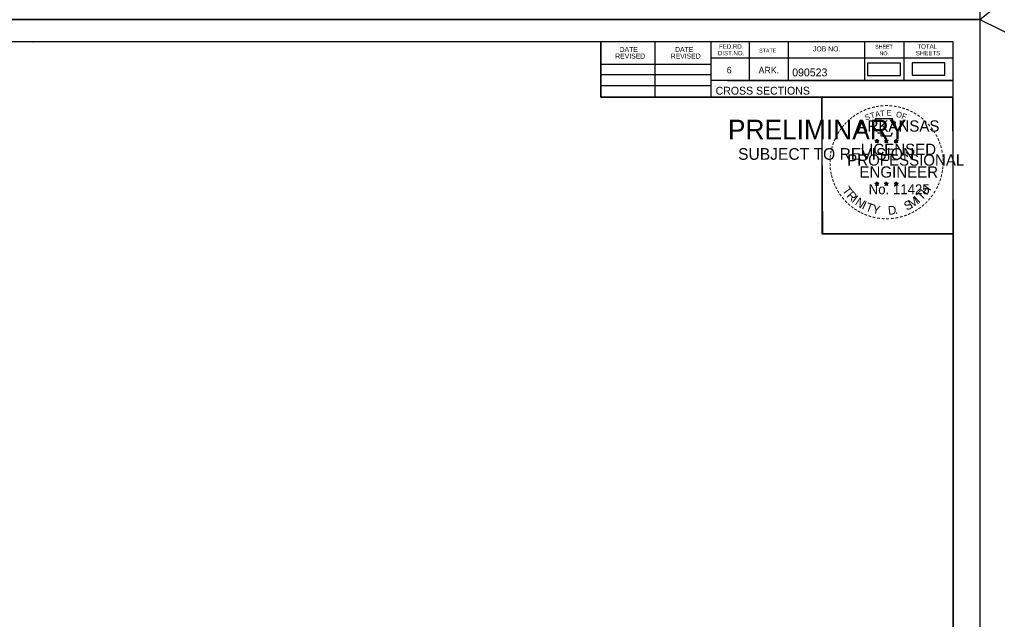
# Model space of a CAD drawing. Extents: x 1406028 to 1412453, y 321733 to 325986.
# Drawn here: x 1406582.1 to 1406755.9, y 322892.7 to 322999.4 of the extents above; entities that cross this region are included whole.
import ezdxf

# ---------------------------------------------------------------- set-up
doc = ezdxf.new("R2010")
doc.units = 0
for name, color, linetype in [('R_Border', 7, 'Continuous'), ('R_Border PE', 7, 'Continuous'), ('R_Border Prem', 7, 'Continuous'), ('R_Fin Surface', 7, 'Continuous'), ('R_No Plot', 7, 'Continuous'), ('R_Water', 7, 'Continuous')]:
    doc.layers.add(name, color=color, linetype=linetype)

msp = doc.modelspace()

# ---------------------------------------------------------------- linework, layer by layer
at = {"layer": 'R_Border'}
for p, q in [((1406431.88, 322995.46), (1406748.06, 322995.46)), ((1406584.4, 322995.2), (1406584.4, 322995.2)), ((1406584.4, 322995.2), (1406584.4, 322995.2)), ((1406685.42, 322985.58), (1406685.42, 322995.46)), ((1406695.1, 322985.58), (1406695.1, 322995.46)), ((1406704.96, 322995.46), (1406704.96, 322985.58)), ((1406711.8, 322995.46), (1406711.8, 322988.52)), ((1406718.74, 322995.46), (1406718.74, 322988.52)), ((1406732.32, 322995.46), (1406732.32, 322988.52)), ((1406739.26, 322995.46), (1406739.26, 322988.52)), ((1406748.06, 322790), (1406748.06, 322995.46)), ((1406685.42, 322991.44), (1406704.96, 322991.44)), ((1406748.06, 322992.52), (1406704.96, 322992.52)), ((1406748.06, 322992.54), (1406748.06, 322992.54)), ((1406685.42, 322989.58), (1406704.96, 322989.58)), ((1406685.42, 322987.64), (1406704.96, 322987.64)), ((1406748.06, 322988.52), (1406704.96, 322988.52)), ((1406707.92, 322988.52), (1406748.06, 322988.52)), ((1406748.06, 322985.58), (1406685.42, 322985.58))]:
    msp.add_line(p, q, dxfattribs=at)
at = {"layer": 'R_Border PE'}
for p, q in [((1406734.15, 322977.84), (1406734.5, 322977.73)), ((1406734.15, 322977.84), (1406734.4, 322977.79)), ((1406734.15, 322977.84), (1406734.38, 322977.72)), ((1406734.28, 322977.43), (1406734.5, 322977.73)), ((1406734.28, 322977.43), (1406734.41, 322977.67)), ((1406734.28, 322977.43), (1406734.49, 322977.65)), ((1406734.5, 322978.09), (1406734.46, 322977.84)), ((1406734.71, 322977.43), (1406734.49, 322977.64)), ((1406734.5, 322977.73), (1406734.5, 322978.09)), ((1406734.5, 322978.09), (1406734.55, 322977.84)), ((1406734.84, 322977.84), (1406734.5, 322977.73)), ((1406734.71, 322977.43), (1406734.5, 322977.73)), ((1406734.84, 322977.84), (1406734.56, 322977.79)), ((1406734.71, 322977.43), (1406734.57, 322977.72)), ((1406734.84, 322977.84), (1406734.64, 322977.74)), ((1406735.82, 322977.84), (1406736.17, 322977.73)), ((1406735.82, 322977.84), (1406736.07, 322977.79)), ((1406735.82, 322977.84), (1406736.05, 322977.72)), ((1406735.95, 322977.43), (1406736.17, 322977.73)), ((1406735.95, 322977.43), (1406736.08, 322977.67)), ((1406735.95, 322977.43), (1406736.16, 322977.65)), ((1406736.17, 322978.09), (1406736.13, 322977.84)), ((1406736.38, 322977.43), (1406736.16, 322977.64)), ((1406736.17, 322977.73), (1406736.17, 322978.09)), ((1406736.17, 322978.09), (1406736.22, 322977.84)), ((1406736.51, 322977.84), (1406736.17, 322977.73)), ((1406736.38, 322977.43), (1406736.17, 322977.73)), ((1406736.51, 322977.84), (1406736.23, 322977.79)), ((1406736.38, 322977.43), (1406736.24, 322977.72)), ((1406736.51, 322977.84), (1406736.31, 322977.74)), ((1406737.58, 322977.83), (1406737.93, 322977.72)), ((1406737.58, 322977.83), (1406737.83, 322977.78)), ((1406737.58, 322977.83), (1406737.82, 322977.7)), ((1406737.71, 322977.42), (1406737.93, 322977.72)), ((1406737.71, 322977.42), (1406737.84, 322977.66)), ((1406737.71, 322977.42), (1406737.93, 322977.64)), ((1406737.93, 322978.08), (1406737.89, 322977.83)), ((1406737.93, 322977.72), (1406737.93, 322978.08)), ((1406737.93, 322978.08), (1406737.98, 322977.83)), ((1406738.28, 322977.83), (1406737.93, 322977.72)), ((1406738.14, 322977.42), (1406737.93, 322977.72)), ((1406738.14, 322977.42), (1406737.93, 322977.63)), ((1406738.28, 322977.83), (1406737.99, 322977.78)), ((1406738.14, 322977.42), (1406738.01, 322977.71)), ((1406738.28, 322977.83), (1406738.07, 322977.72)), ((1406734.14, 322970.27), (1406734.49, 322970.15)), ((1406734.14, 322970.27), (1406734.4, 322970.22)), ((1406734.14, 322970.27), (1406734.38, 322970.14)), ((1406734.49, 322970.52), (1406734.45, 322970.27)), ((1406734.49, 322970.15), (1406734.49, 322970.52)), ((1406734.49, 322970.52), (1406734.54, 322970.27)), ((1406734.84, 322970.27), (1406734.49, 322970.15)), ((1406734.84, 322970.27), (1406734.55, 322970.22)), ((1406734.84, 322970.27), (1406734.64, 322970.16)), ((1406735.81, 322970.27), (1406736.16, 322970.15)), ((1406735.81, 322970.27), (1406736.07, 322970.22)), ((1406735.81, 322970.27), (1406736.05, 322970.14)), ((1406736.16, 322970.52), (1406736.12, 322970.27)), ((1406736.16, 322970.15), (1406736.16, 322970.52)), ((1406736.16, 322970.52), (1406736.21, 322970.27)), ((1406736.51, 322970.27), (1406736.16, 322970.15)), ((1406736.51, 322970.27), (1406736.22, 322970.22)), ((1406736.51, 322970.27), (1406736.3, 322970.16)), ((1406737.58, 322970.26), (1406737.93, 322970.14)), ((1406737.58, 322970.26), (1406737.83, 322970.21)), ((1406737.58, 322970.26), (1406737.82, 322970.13)), ((1406737.93, 322970.51), (1406737.89, 322970.26)), ((1406737.93, 322970.14), (1406737.93, 322970.51)), ((1406737.93, 322970.51), (1406737.98, 322970.26)), ((1406738.28, 322970.26), (1406737.93, 322970.14)), ((1406738.28, 322970.26), (1406737.99, 322970.21)), ((1406738.28, 322970.26), (1406738.07, 322970.15)), ((1406734.28, 322969.86), (1406734.49, 322970.15)), ((1406734.28, 322969.86), (1406734.4, 322970.1)), ((1406734.28, 322969.86), (1406734.49, 322970.07)), ((1406734.71, 322969.86), (1406734.49, 322970.15)), ((1406734.71, 322969.86), (1406734.49, 322970.07)), ((1406734.71, 322969.86), (1406734.57, 322970.15)), ((1406735.95, 322969.86), (1406736.16, 322970.15)), ((1406735.95, 322969.86), (1406736.07, 322970.1)), ((1406735.95, 322969.86), (1406736.16, 322970.07)), ((1406736.37, 322969.86), (1406736.16, 322970.15)), ((1406736.37, 322969.86), (1406736.16, 322970.07)), ((1406736.37, 322969.86), (1406736.24, 322970.15)), ((1406737.71, 322969.85), (1406737.93, 322970.14)), ((1406737.71, 322969.85), (1406737.84, 322970.09)), ((1406737.71, 322969.85), (1406737.93, 322970.06)), ((1406738.14, 322969.85), (1406737.93, 322970.14)), ((1406738.14, 322969.85), (1406737.93, 322970.06)), ((1406738.14, 322969.85), (1406738, 322970.14))]:
    msp.add_line(p, q, dxfattribs=at)
for points in [[(1406734.19, 322981.72), (1406734.46, 322980.89)], [(1406737.7, 322980.79), (1406737.84, 322981.08), (1406737.16, 322981.05), (1406737.3, 322981.72), (1406734.19, 322981.72)], [(1406734.68, 322979.29), (1406734.68, 322979.21), (1406735.24, 322979.19), (1406735.19, 322978.71), (1406737.06, 322978.71), (1406737.26, 322979.25)], [(1406734.5, 322978.09), (1406734.71, 322977.43), (1406734.15, 322977.84), (1406734.84, 322977.84), (1406734.28, 322977.43), (1406734.5, 322978.09)], [(1406736.17, 322978.09), (1406736.38, 322977.43), (1406735.82, 322977.84), (1406736.51, 322977.84), (1406735.95, 322977.43), (1406736.17, 322978.09)], [(1406737.93, 322978.08), (1406738.14, 322977.42), (1406737.58, 322977.83), (1406738.28, 322977.83), (1406737.71, 322977.42), (1406737.93, 322978.08)], [(1406734.49, 322970.52), (1406734.71, 322969.86), (1406734.14, 322970.27), (1406734.84, 322970.27), (1406734.28, 322969.86), (1406734.49, 322970.52)], [(1406736.16, 322970.52), (1406736.37, 322969.86), (1406735.81, 322970.27), (1406736.51, 322970.27), (1406735.95, 322969.86), (1406736.16, 322970.52)], [(1406737.93, 322970.51), (1406738.14, 322969.85), (1406737.58, 322970.26), (1406738.28, 322970.26), (1406737.71, 322969.85), (1406737.93, 322970.51)]]:
    msp.add_lwpolyline(points, dxfattribs=at)
for centre, radius in [((1406734.5, 322977.73), 0.172), ((1406734.5, 322977.73), 0.145), ((1406734.5, 322977.73), 0.116), ((1406734.5, 322977.73), 0.0991), ((1406734.5, 322977.73), 0.0747), ((1406734.5, 322977.73), 0.0495), ((1406734.5, 322977.73), 0.0296), ((1406736.17, 322977.73), 0.172), ((1406736.17, 322977.73), 0.145), ((1406736.17, 322977.73), 0.116), ((1406736.17, 322977.73), 0.0991), ((1406736.17, 322977.73), 0.0747), ((1406736.17, 322977.73), 0.0495), ((1406736.17, 322977.73), 0.0296), ((1406737.93, 322977.72), 0.172), ((1406737.93, 322977.72), 0.145), ((1406737.93, 322977.72), 0.116), ((1406737.93, 322977.72), 0.0991), ((1406737.93, 322977.72), 0.0747), ((1406737.93, 322977.72), 0.0495), ((1406737.93, 322977.72), 0.0296), ((1406734.49, 322970.15), 0.172), ((1406734.49, 322970.15), 0.145), ((1406734.49, 322970.15), 0.116), ((1406734.49, 322970.15), 0.0991), ((1406734.49, 322970.15), 0.0747), ((1406734.49, 322970.15), 0.0495), ((1406736.16, 322970.15), 0.172), ((1406736.16, 322970.15), 0.145), ((1406736.16, 322970.15), 0.116), ((1406736.16, 322970.15), 0.0991), ((1406736.16, 322970.15), 0.0747), ((1406736.16, 322970.15), 0.0495), ((1406737.93, 322970.14), 0.172), ((1406737.93, 322970.14), 0.145), ((1406737.93, 322970.14), 0.116), ((1406737.93, 322970.14), 0.0991), ((1406737.93, 322970.14), 0.0747), ((1406734.49, 322970.15), 0.0296), ((1406736.16, 322970.15), 0.0296), ((1406737.93, 322970.14), 0.0495), ((1406737.93, 322970.14), 0.0296)]:
    msp.add_circle(centre, radius, dxfattribs=at)
at = {"layer": 'R_Fin Surface'}
for points in [[(1406732.85, 322989.41), (1406738.68, 322989.41), (1406738.68, 322991.59), (1406732.85, 322991.59)], [(1406740.76, 322989.47), (1406746.59, 322989.47), (1406746.59, 322991.66), (1406740.76, 322991.66)]]:
    msp.add_lwpolyline(points, close=True, dxfattribs=at)
at = {"layer": 'R_No Plot'}
for p, q in [((1406419.48, 322999.36), (1406752.82, 322999.36)), ((1406724.1, 322963.13), (1406724.1, 322963.13))]:
    msp.add_line(p, q, dxfattribs=at)
for points in [[(1406419.48, 323212.7), (1406752.82, 323212.7), (1406752.82, 322999.36), (1406419.48, 322999.36)], [(1406419.48, 322999.36), (1406752.82, 322999.36), (1406752.82, 322786.02), (1406419.48, 322786.02)], [(1406665.8, 322995.46), (1406685.42, 322995.46), (1406685.42, 322985.58), (1406701.54, 322985.58), (1406724.73, 322985.58), (1406724.73, 322961.25), (1406748.06, 322961.25), (1406748.06, 322790), (1406431.88, 322790), (1406431.88, 322995.46)], [(1406724.73, 322985.58), (1406747.94, 322985.58), (1406748.06, 322961.25), (1406724.86, 322961.25)]]:
    msp.add_lwpolyline(points, close=True, dxfattribs=at)
at = {"layer": 'R_Water'}
for q in [(1406884.16, 323105.96), (1406892.15, 322929.92)]:
    msp.add_line((1406752.82, 322999.36), q, dxfattribs=at)

# ---------------------------------------------------------------- texts
at = {"layer": 'R_Border'}
for s, height, p in [('FED.RD.', 0.782, (1406706.44, 322994.18)), ('JOB NO.', 0.879, (1406723.14, 322993.7)), ('SHEET', 0.684, (1406734.18, 322994.18)), ('TOTAL', 0.782, (1406741.7, 322994.18)), ('REVISED', 0.879, (1406687.98, 322992.42)), ('DATE', 0.879, (1406688.76, 322993.6)), ('REVISED', 0.879, (1406697.84, 322992.42)), ('DATE', 0.879, (1406698.62, 322993.6)), ('DIST.NO.', 0.782, (1406706.24, 322993)), ('STATE', 0.684, (1406713.56, 322993.5)), ('NO.', 0.684, (1406734.96, 322993)), ('SHEETS', 0.782, (1406741.42, 322993)), ('6', 1.17, (1406707.8, 322989.78)), ('ARK.', 1.172, (1406713.46, 322989.78)), ('090523', 1.4, (1406719.44, 322989.26)), ('CROSS SECTIONS', 1.4, (1406705.83, 322986.01))]:
    msp.add_text(s, height=height, rotation=360, dxfattribs=at).set_placement(p)
at = {"layer": 'R_Border PE'}
for s, height, rotation, p in [('-', 1.6, 5.8968, (1406735.09, 322983.36)), ('-', 1.6, 0.1862, (1406735.87, 322983.43)), ('-', 1.6, 357.743, (1406736.59, 322983.42)), ('-', 1.6, 36.2317, (1406730.49, 322981.49)), ('-', 1.6, 34.0636, (1406731.07, 322981.89)), ('-', 1.6, 28.7918, (1406731.67, 322982.26)), ('-', 1.6, 24.3072, (1406732.3, 322982.57)), ('S', 1, 21.594, (1406732.54, 322981.39)), ('-', 1.6, 19.1761, (1406732.94, 322982.84)), ('T', 1, 16.4036, (1406733.46, 322981.73)), ('-', 1.6, 13.6301, (1406733.69, 322983.08)), ('A', 1, 11.2132, (1406734.28, 322981.98)), ('-', 1.6, 10.2193, (1406734.36, 322983.25)), ('T', 1, 6.0228, (1406735.13, 322982.14)), ('E', 1, 0.8323, (1406736.24, 322982.25)), ('-', 1.6, 352.1617, (1406737.33, 322983.36)), ('O', 1, 350.4515, (1406737.84, 322982.04)), ('-', 1.6, 347.2049, (1406738.05, 322983.25)), ('F', 1, 340.0707, (1406738.8, 322981.81)), ('-', 1.6, 342.3362, (1406738.69, 322983.09)), ('-', 1.6, 337.8551, (1406739.42, 322982.87)), ('-', 1.6, 334.1211, (1406740.05, 322982.6)), ('-', 1.6, 329.6409, (1406740.63, 322982.31)), ('-', 1.6, 325.8627, (1406741.27, 322981.95)), ('-', 1.6, 50.6142, (1406728.73, 322979.73)), ('-', 1.6, 48.423, (1406729.14, 322980.22)), ('-', 1.6, 42.9622, (1406729.59, 322980.7)), ('-', 1.6, 38.9507, (1406730.02, 322981.11)), ('ARKANSAS', 2, 360, (1406731.04, 322979.43)), ('-', 1.6, 320.5297, (1406741.88, 322981.53)), ('-', 1.6, 315.5786, (1406742.48, 322981.04)), ('-', 1.6, 309.8797, (1406743.05, 322980.49)), ('-', 1.6, 62.8713, (1406727.68, 322978.03)), ('-', 1.6, 58.0706, (1406728, 322978.64)), ('-', 1.6, 54.2325, (1406728.32, 322979.17)), ('-', 1.6, 306.6522, (1406743.58, 322979.89)), ('-', 1.4, 303.6753, (1406744.06, 322979.32)), ('-', 1.6, 299.6684, (1406744.38, 322978.71)), ('-', 1.6, 72.3945, (1406727.21, 322976.78)), ('-', 1.6, 67.7743, (1406727.42, 322977.41)), ('LICENSED', 2, 360, (1406731.64, 322975.28)), ('DWB', 0.01, 360, (1406734.48, 322977.72)), ('DWB', 0.01, 360, (1406736.15, 322977.72)), ('DWB', 0.01, 360, (1406737.92, 322977.71)), ('-', 1.6, 294.6628, (1406744.71, 322978.1)), ('-', 1.6, 290.5728, (1406744.96, 322977.52)), ('-', 1.6, 81.2013, (1406726.88, 322975.36)), ('-', 1.6, 75.461, (1406727.01, 322976.07)), ('-', 1.6, 285.1233, (1406745.2, 322976.94)), ('-', 1.6, 280.5493, (1406745.4, 322976.2)), ('-', 1.6, 276.5962, (1406745.56, 322975.43)), ('-', 1.6, 94.1959, (1406726.81, 322973.24)), ('-', 1.6, 89.0622, (1406726.78, 322973.97)), ('-', 1.6, 85.1863, (1406726.8, 322974.67)), ('PROFESSIONAL', 2, 360, (1406729.22, 322973.38)), ('-', 1.6, 274.3301, (1406745.62, 322974.71)), ('-', 1.6, 269.9407, (1406745.65, 322974.08)), ('-', 1.6, 98.9479, (1406726.88, 322972.57)), ('-', 1.6, 101.7149, (1406727.02, 322971.84)), ('ENGINEER', 2, 360, (1406731.4, 322971.25)), ('-', 1.6, 260.9953, (1406745.56, 322972.76)), ('-', 1.6, 263.5172, (1406745.63, 322973.41)), ('-', 1.6, 105.4578, (1406727.18, 322971.25)), ('-', 1.6, 109.0874, (1406727.39, 322970.61)), ('-', 1.6, 114.0643, (1406727.65, 322970.02)), ('-', 1.6, 247.8887, (1406745.05, 322970.69)), ('-', 1.6, 252.8681, (1406745.27, 322971.36)), ('-', 1.6, 255.7626, (1406745.45, 322972.08)), ('-', 1.6, 115.7289, (1406727.95, 322969.4)), ('-', 1.6, 120.4471, (1406728.31, 322968.81)), ('T', 1.54, 306.0406, (1406728.25, 322968.99)), ('R', 1.54, 314.005, (1406729.01, 322967.95)), ('No. 11425', 1.757, 360, (1406733.03, 322968.3)), ('DWB', 0.01, 360, (1406734.48, 322970.15)), ('DWB', 0.01, 360, (1406736.15, 322970.15)), ('DWB', 0.01, 360, (1406737.92, 322970.14)), ('T', 1.54, 46.6444, (1406742.48, 322967.09)), ('H', 1.54, 54.6088, (1406743.37, 322968.03)), ('-', 1.6, 239.0712, (1406744.39, 322969.31)), ('-', 1.6, 244.6197, (1406744.79, 322970.06)), ('-', 1.6, 125.8934, (1406728.71, 322968.25)), ('-', 1.6, 130.7181, (1406729.18, 322967.7)), ('-', 1.6, 134.2238, (1406729.69, 322967.16)), ('I', 1.54, 321.9694, (1406729.92, 322967.01)), ('N', 1.54, 326.5002, (1406730.48, 322966.54)), ('I', 1.54, 335.3603, (1406731.69, 322965.76)), ('T', 1.54, 339.8912, (1406732.35, 322965.43)), ('S', 1.54, 26.9312, (1406739.8, 322965.35)), ('M', 1.54, 32.6563, (1406740.64, 322965.76)), ('I', 1.54, 42.1136, (1406741.92, 322966.61)), ('-', 1.6, 225.7653, (1406743.08, 322967.52)), ('-', 1.6, 231.2538, (1406743.56, 322968.09)), ('-', 1.6, 233.8452, (1406743.99, 322968.65)), ('-', 1.6, 138.9338, (1406730.22, 322966.69)), ('-', 1.6, 144.6463, (1406730.77, 322966.29)), ('-', 1.6, 148.0898, (1406731.33, 322965.92)), ('-', 1.6, 151.5704, (1406731.91, 322965.59)), ('-', 1.6, 154.6002, (1406732.44, 322965.34)), ('Y', 1.54, 347.8556, (1406733.57, 322964.98)), ('D', 1.54, 6.3969, (1406736.55, 322964.62)), ('.', 1.54, 13.7642, (1406737.75, 322964.75)), ('-', 1.6, 207.3568, (1406740.92, 322965.81)), ('-', 1.6, 212.2491, (1406741.48, 322966.16)), ('-', 1.6, 215.7363, (1406742.01, 322966.54)), ('-', 1.6, 221.0851, (1406742.56, 322967.01)), ('-', 1.6, 158.5612, (1406733.06, 322965.09)), ('-', 1.6, 162.7983, (1406733.75, 322964.88)), ('-', 1.6, 167.5555, (1406734.46, 322964.71)), ('-', 1.6, 173.1155, (1406735.23, 322964.6)), ('-', 1.6, 176.5183, (1406735.98, 322964.55)), ('-', 1.6, 181.5918, (1406736.73, 322964.57)), ('-', 1.6, 185.8167, (1406737.53, 322964.64)), ('-', 1.6, 191.2858, (1406738.27, 322964.78)), ('-', 1.6, 195.4743, (1406739, 322964.98)), ('-', 1.6, 200.7184, (1406739.68, 322965.22)), ('-', 1.6, 204.2516, (1406740.3, 322965.49))]:
    msp.add_text(s, height=height, rotation=rotation, dxfattribs=at).set_placement(p)
at = {"layer": 'R_Border Prem'}
for s, height, p in [('PRELIMINARY', 3.5, (1406708.01, 322978.05)), ('DWB', 0.01, (1406708.76, 322979.9)), ('SUBJECT TO REVISION', 2.0751, (1406709.82, 322974.42))]:
    msp.add_text(s, height=height, rotation=360, dxfattribs=at).set_placement(p)

doc.saveas('drawing.dxf')
